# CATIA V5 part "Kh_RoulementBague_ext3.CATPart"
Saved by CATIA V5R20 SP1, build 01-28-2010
Part number: Roulement bague ext 3
Bounding box of the stored display mesh (mm): x -20 to 20, y -20 to 20, z -8 to 4
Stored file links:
  G:\Khaled_CFAO_2011\SIL\SIL_GR1\tmerino\Khaled\CAD_Thinkmotion\Kh_RoulementBague_ext3.CATPart
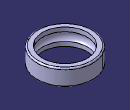
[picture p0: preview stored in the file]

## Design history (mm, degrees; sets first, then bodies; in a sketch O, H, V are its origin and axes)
Body1 (main body)
  Sketch1 on yz-plane, origin (0, 0, 0), H (0, 1, 0), V (0, 0, 1)
    line L1 (-20, -8) -> (-20, 4)
    line L2 (-20, 4) -> (-16, 4)
    line L3 (-20, -8) -> (-16, -8)
    line L4 (-16, 4) -> (-16, 1)
    line L5 (-16, -8) -> (-16, -5)
    arc A1 centre (-14.25, -2) radius 3.4731 from (-16, 1) to (-16, -5) ccw
    length L2 = 4
    length L3 = 4
    length L1 = 12
    length L4 = 3
    length L5 = 3
    distance L4 V = 16
    vertical: L1 V, L4 V, L5 V
    horizontal: L2 H, L3 H
  Shaft1: profile Sketch1, axis Sketch1.V, angle 360
  Fillet1: radius 1, on edge [face of Shaft1 from Sketch1.L1 | face of Shaft1 from Sketch1.L2]
  Fillet2: radius 1, on edge [face of Shaft1 from Sketch1.L3 | face of Shaft1 from Sketch1.L1]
